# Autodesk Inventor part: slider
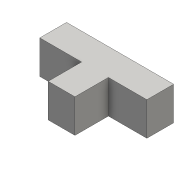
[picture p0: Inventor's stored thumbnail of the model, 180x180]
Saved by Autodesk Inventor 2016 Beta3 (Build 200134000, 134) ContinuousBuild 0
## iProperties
Created: 2016-03
Part Number: slider
Material: Generic
Document SubType Name: Modeling
Designer: Gaurav
Density: 1 g/cm^3
Appearance: Default
Author: Gaurav
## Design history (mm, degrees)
sketch "Sketch1"
  geometry: L1 (4, 5)-(4, -5); L2 (4, -5)-(-4, -5); L3 (-4, -5)-(-4, 5); L4 (-4, 5)-(4, -5); L5 (4, 5)-(-4, -5); L6 (15.5, 5)-(15.5, 13); L7 (15.5, 13)-(-16.5, 13); L8 (-16.5, 13)-(-16.5, 5); L9 (-16.5, 5)-(-4, 5); L10 (4, 5)-(15.5, 5); 1 further point
  constraints: 20 end point, 4 parallel, 2 horizontal, 2 midpoint, 2 perpendicular
  dimensions: "d0" = 8 distance of L1.end L2.end; "d1" = 10 distance of L1.start L1.end; "d2" = 32 distance of L7.end L6.end; "d3" = 8 distance of L6.end L6.start
extrude "Extrusion1" new body sketch "Sketch1" distance "d4" = 10; taper "d5" = 0 deg
body "Solid1"
